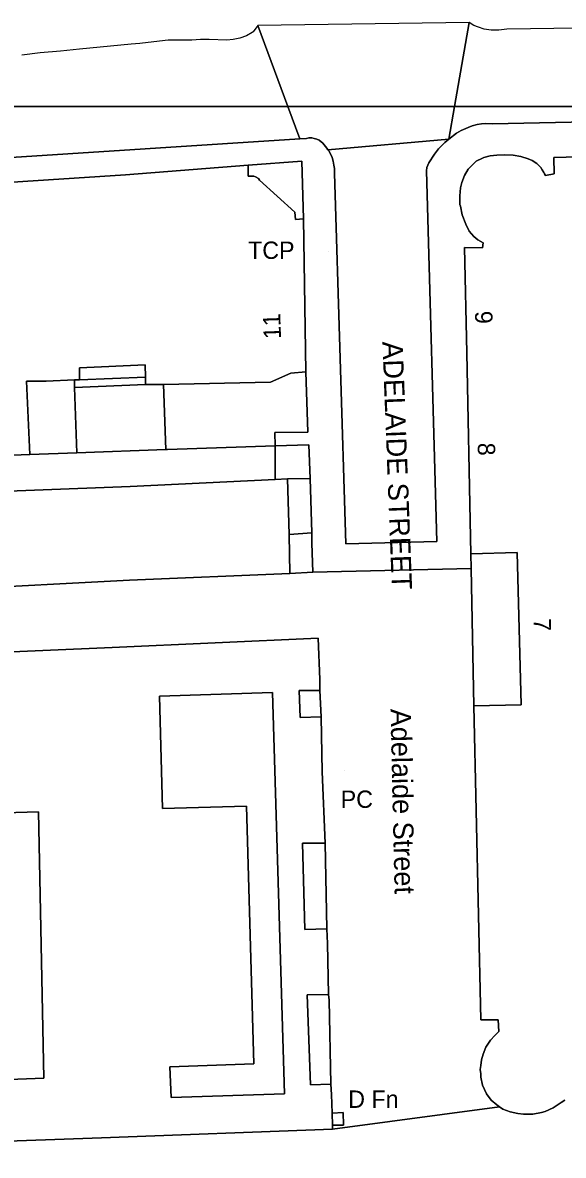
# Model space of a CAD drawing. Extents: x 529240 to 530363, y 179600 to 180767.
# Drawn here: x 530122.5 to 530169.2, y 180523.5 to 180621.2 of the extents above; entities that cross this region are included whole.
import ezdxf

# ---------------------------------------------------------------- set-up
doc = ezdxf.new("R2010")
doc.units = 0
for name, color, linetype in [('Building', 7, 'Continuous'), ('General surface', 7, 'Continuous'), ('Road Or Track', 7, 'Continuous'), ('Roadside', 7, 'Continuous'), ('Structure', 7, 'Continuous'), ('Unclassified', 7, 'Continuous')]:
    doc.layers.add(name, color=color, linetype=linetype)

msp = doc.modelspace()

# ---------------------------------------------------------------- linework, layer by layer
at = {"layer": 'Building'}
for points in [[(530206.3, 180610.65), (530168.35, 180609.6), (530168.4, 180608.2), (530167.65, 180608.05), (530167.55, 180608.2), (530167.5, 180608.3), (530167.35, 180608.55), (530167.25, 180608.75), (530166.9, 180609.1), (530166.5, 180609.35), (530166.15, 180609.5), (530165.5, 180609.7), (530164.85, 180609.8), (530164.1, 180609.85), (530163.45, 180609.8), (530162.85, 180609.75), (530162.3, 180609.6), (530162.2, 180609.55), (530161.65, 180609.3), (530160.95, 180608.6), (530160.65, 180608.05), (530160.4, 180607.45), (530160.3, 180607), (530160.25, 180606.3), (530160.25, 180605.55), (530160.3, 180605.4), (530160.45, 180604.65), (530160.75, 180603.85), (530161.05, 180603.25), (530161.45, 180602.8), (530161.8, 180602.5), (530162.25, 180602.25), (530162.2, 180601.8), (530160.65, 180601.85), (530160.85, 180592.75), (530161.15, 180576.8), (530161.2, 180575.4), (530165.2, 180575.5), (530165.55, 180562.35), (530161.45, 180562.25), (530162.05, 180535.15), (530163.55, 180535.15), (530163.6, 180534.15), (530163.25, 180533.8), (530162.9, 180533.4), (530162.5, 180532.8), (530162.25, 180532.2), (530162.1, 180531.7), (530162.05, 180531.2), (530162, 180530.85), (530162.05, 180530.5), (530162.05, 180530.2), (530162.2, 180529.5), (530162.55, 180528.75), (530162.95, 180528.2), (530163.45, 180527.8), (530163.66, 180527.65), (530163.95, 180527.45), (530164.6, 180527.2), (530165.25, 180527.05), (530165.75, 180527), (530166.55, 180527), (530167.3, 180527.15), (530167.6, 180527.25), (530168.3, 180527.55), (530169, 180528), (530169.3, 180528.2)], [(530161.15, 180576.8), (530160.85, 180592.75), (530160.65, 180601.85), (530162.2, 180601.8), (530162.25, 180602.25), (530161.8, 180602.5), (530161.45, 180602.8), (530161.05, 180603.25), (530160.75, 180603.85), (530160.45, 180604.65), (530160.3, 180605.4), (530160.25, 180605.55), (530160.25, 180606.3), (530160.3, 180607), (530160.4, 180607.45), (530160.65, 180608.05), (530160.95, 180608.6), (530161.65, 180609.3), (530162.2, 180609.55), (530162.3, 180609.6), (530162.85, 180609.75), (530163.45, 180609.8), (530164.1, 180609.85), (530164.85, 180609.8), (530165.5, 180609.7), (530166.15, 180609.5), (530166.5, 180609.35), (530166.9, 180609.1), (530167.25, 180608.75), (530167.35, 180608.55), (530167.5, 180608.3), (530167.55, 180608.2), (530167.65, 180608.05), (530168.4, 180608.2), (530168.35, 180609.6), (530206.3, 180610.65)], [(530091.2, 180605.2), (530113.6, 180606.95), (530131.35, 180608.1), (530141.95, 180608.95)], [(530116.3, 180583.7), (530123.1, 180583.95), (530122.8, 180590.3), (530124.5, 180590.3), (530126.95, 180590.4), (530127.4, 180590.4), (530127.4, 180591.45), (530133.05, 180591.7), (530133.1, 180590.65), (530133.1, 180590), (530134.65, 180590), (530143.9, 180590.2), (530145.65, 180591), (530146.95, 180591.1), (530146.75, 180604.3), (530146.05, 180604.25), (530146, 180604.9), (530142.95, 180607.65), (530142.85, 180607.8), (530142.6, 180607.95), (530142.45, 180608), (530141.95, 180608), (530141.95, 180608.95), (530131.35, 180608.1), (530113.6, 180606.95)], [(530141.95, 180608.95), (530141.95, 180608), (530142.45, 180608), (530142.6, 180607.95), (530142.85, 180607.8), (530142.95, 180607.65), (530146, 180604.9), (530146.05, 180604.25), (530146.75, 180604.3)], [(530146.75, 180604.3), (530146.95, 180591.1)], [(530127.4, 180590.4), (530127.4, 180591.45), (530133.05, 180591.7), (530133.1, 180590.65)], [(530133.1, 180590.65), (530133.1, 180590)], [(530134.65, 180590), (530143.9, 180590.2), (530145.65, 180591), (530146.95, 180591.1)], [(530146.95, 180591.1), (530147.1, 180585.9)], [(530123.1, 180583.95), (530122.8, 180590.3), (530124.5, 180590.3)], [(530124.5, 180590.3), (530126.95, 180590.4)], [(530126.95, 180590.4), (530127.4, 180590.4)], [(530133.1, 180590), (530134.65, 180590)], [(530134.65, 180590), (530134.85, 180584.4)], [(530144.3, 180584.7), (530144.25, 180585.85), (530147.1, 180585.9)], [(530109.95, 180583.45), (530116.3, 180583.7), (530123.1, 180583.95)], [(530123.1, 180583.95), (530127.15, 180584.1)], [(530127.15, 180584.1), (530134.85, 180584.4)], [(530134.85, 180584.4), (530135, 180584.4), (530144.3, 180584.7)], [(530144.3, 180584.7), (530144.3, 180581.8)], [(530144.3, 180581.8), (530145.35, 180581.85)], [(530145.35, 180581.85), (530145.5, 180577.05)], [(530115.95, 180580.1), (530115.95, 180580.6), (530131.75, 180581.2), (530144.3, 180581.8)], [(530145.5, 180577.05), (530145.55, 180573.7)], [(530161.2, 180575.4), (530161.15, 180576.8)], [(530161.45, 180562.25), (530165.55, 180562.35), (530165.2, 180575.5), (530161.2, 180575.4)], [(530161.2, 180575.4), (530161.22, 180574.13)], [(530161.22, 180574.13), (530161.45, 180562.25)], [(530145.55, 180573.7), (530131.7, 180573.1), (530116.4, 180572.3)], [(530135.3, 180528.45), (530135.2, 180531.1), (530142.45, 180531.35), (530141.8, 180553.6), (530134.55, 180553.4), (530134.3, 180563.1), (530144.05, 180563.4), (530145.1, 180528.75), (530135.3, 180528.45)], [(530163.66, 180527.65), (530163.45, 180527.8), (530162.95, 180528.2), (530162.55, 180528.75), (530162.2, 180529.5), (530162.05, 180530.2), (530162.05, 180530.5), (530162, 180530.85), (530162.05, 180531.2), (530162.1, 180531.7), (530162.25, 180532.2), (530162.5, 180532.8), (530162.9, 180533.4), (530163.25, 180533.8), (530163.6, 180534.15), (530163.55, 180535.15), (530162.05, 180535.15), (530161.45, 180562.25)], [(530100.85, 180552.35), (530111.15, 180552.75), (530123.85, 180553.1), (530124.3, 180530.1), (530107.15, 180529.45), (530083.85, 180528.65)], [(530169.3, 180528.2), (530169, 180528), (530168.3, 180527.55), (530167.6, 180527.25), (530167.3, 180527.15), (530166.55, 180527), (530165.75, 180527), (530165.25, 180527.05), (530164.6, 180527.2), (530163.95, 180527.45), (530163.66, 180527.65)]]:
    msp.add_lwpolyline(points, dxfattribs=at)
for points in [[(530146.75, 180604.3), (530146.6, 180609.3), (530141.95, 180608.95), (530141.95, 180608), (530142.45, 180608), (530142.6, 180607.95), (530142.85, 180607.8), (530142.95, 180607.65), (530146, 180604.9), (530146.05, 180604.25)], [(530133.1, 180590.65), (530133.05, 180591.7), (530127.4, 180591.45), (530127.4, 180590.4)], [(530134.65, 180590), (530134.85, 180584.4), (530135, 180584.4), (530144.3, 180584.7), (530144.25, 180585.85), (530147.1, 180585.9), (530146.95, 180591.1), (530145.65, 180591), (530143.9, 180590.2)], [(530115.95, 180580.1), (530115.95, 180580.6), (530131.75, 180581.2), (530144.3, 180581.8), (530144.3, 180584.7), (530135, 180584.4), (530134.85, 180584.4), (530127.15, 180584.1), (530123.1, 180583.95), (530116.3, 180583.7), (530109.95, 180583.45), (530109.9, 180579.85)], [(530145.35, 180581.85), (530144.3, 180581.8), (530131.75, 180581.2), (530115.95, 180580.6), (530115.95, 180580.1), (530116.35, 180572.7), (530116.4, 180572.3), (530131.7, 180573.1), (530145.55, 180573.7), (530145.5, 180577.05)], [(530161.22, 180574.13), (530161.45, 180562.25), (530165.55, 180562.35), (530165.2, 180575.5), (530161.2, 180575.4)], [(530135.3, 180528.45), (530145.1, 180528.75), (530144.05, 180563.4), (530134.3, 180563.1), (530134.55, 180553.4), (530141.8, 180553.6), (530142.45, 180531.35), (530135.2, 180531.1)], [(530083.13, 180550.2), (530083.15, 180549.55), (530083.8, 180530.7), (530083.85, 180528.65), (530107.15, 180529.45), (530124.3, 180530.1), (530123.85, 180553.1), (530111.15, 180552.75), (530100.85, 180552.35), (530096.15, 180552.19), (530093.7, 180552.1), (530092.25, 180552.02), (530083.1, 180551.55), (530083.1, 180551.5), (530083.12, 180550.9)]]:
    msp.add_lwpolyline(points, close=True, dxfattribs=at)
at = {"layer": 'General surface'}
for points in [[(530127.4, 180590.4), (530126.95, 180590.4), (530126.95, 180589.75), (530133.1, 180590), (530133.1, 180590.65)], [(530123.1, 180583.95), (530127.15, 180584.1), (530126.95, 180589.75), (530126.95, 180590.4), (530124.5, 180590.3), (530122.8, 180590.3)], [(530134.85, 180584.4), (530134.65, 180590), (530133.1, 180590), (530126.95, 180589.75), (530127.15, 180584.1)], [(530144.3, 180584.7), (530144.3, 180581.8), (530145.35, 180581.85), (530147.3, 180581.9), (530147.2, 180584.8)], [(530147.45, 180577.2), (530147.3, 180581.9), (530145.35, 180581.85), (530145.5, 180577.05)], [(530147.55, 180573.8), (530147.45, 180576.3), (530147.45, 180577.2), (530145.5, 180577.05), (530145.55, 180573.7)], [(530135.3, 180528.45), (530145.1, 180528.75), (530144.05, 180563.4), (530134.3, 180563.1), (530134.55, 180553.4), (530141.8, 180553.6), (530142.45, 180531.35), (530135.2, 180531.1)], [(530148.25, 180561.3), (530148.15, 180563.6), (530146.35, 180563.6), (530146.45, 180561.25)], [(530148.75, 180543), (530148.6, 180550.4), (530146.65, 180550.4), (530146.85, 180542.95)], [(530148.9, 180537.35), (530147.05, 180537.3), (530147.35, 180529.55), (530149.1, 180529.6), (530148.95, 180536.85)], [(530149.2, 180527.1), (530149.25, 180526.05), (530150.2, 180526.05), (530150.15, 180527.15)]]:
    msp.add_lwpolyline(points, close=True, dxfattribs=at)
for points in [[(530108.2, 180566.35), (530130.2, 180567.3), (530148, 180568.1), (530148.15, 180564.55), (530148.15, 180563.6), (530148.25, 180561.3), (530148.35, 180556.55), (530148.6, 180550.4), (530148.75, 180543), (530148.8, 180541.75), (530148.9, 180537.35), (530148.95, 180536.85), (530149.1, 180529.6), (530149.15, 180528.7), (530149.2, 180527.1), (530150.15, 180527.15), (530150.2, 180526.05), (530149.25, 180526.05), (530149.25, 180525.7), (530163.66, 180527.65), (530163.45, 180527.8), (530162.95, 180528.2), (530162.55, 180528.75), (530162.2, 180529.5), (530162.05, 180530.2), (530162.05, 180530.5), (530162, 180530.85), (530162.05, 180531.2), (530162.1, 180531.7), (530162.25, 180532.2), (530162.5, 180532.8), (530162.9, 180533.4), (530163.25, 180533.8), (530163.6, 180534.15), (530163.55, 180535.15), (530162.05, 180535.15), (530161.45, 180562.25), (530161.22, 180574.13), (530147.55, 180573.8), (530145.55, 180573.7), (530131.7, 180573.1), (530116.4, 180572.3)], [(530118.75, 180524.6), (530129.3, 180524.95), (530149.25, 180525.7), (530149.25, 180526.05), (530149.2, 180527.1), (530149.15, 180528.7), (530149.1, 180529.6), (530147.35, 180529.55), (530147.05, 180537.3), (530148.9, 180537.35), (530148.8, 180541.75), (530148.75, 180543), (530146.85, 180542.95), (530146.65, 180550.4), (530148.6, 180550.4), (530148.35, 180556.55), (530148.25, 180561.3), (530146.45, 180561.25), (530146.35, 180563.6), (530148.15, 180563.6), (530148.15, 180564.55), (530148, 180568.1), (530130.2, 180567.3), (530108.2, 180566.35)], [(530111.15, 180552.75), (530123.85, 180553.1), (530124.3, 180530.1), (530107.15, 180529.45)]]:
    msp.add_lwpolyline(points, dxfattribs=at)
at = {"layer": 'Road Or Track'}
for points in [[(530077.844, 180614), (530145.396, 180614), (530142.8, 180621), (530142.4, 180620.45), (530142.3, 180620.4), (530141.8, 180620.1), (530141.25, 180619.9), (530140.65, 180619.8), (530140.1, 180619.75), (530138.6, 180619.8), (530137.85, 180619.8), (530137.1, 180619.75), (530135.05, 180619.75), (530134.3, 180619.65), (530132.6, 180619.45), (530131.85, 180619.4), (530127.4, 180618.95), (530125.75, 180618.8), (530124, 180618.65), (530122.4, 180618.45)], [(530176.5, 180620.85), (530164.3, 180620.7), (530163.6, 180620.6), (530162.95, 180620.6), (530162.35, 180620.7), (530161.85, 180620.85), (530161.45, 180621), (530161.05, 180621.25), (530159.788, 180614), (530216, 180614)], [(530159.3, 180611.2), (530159.95, 180611.7), (530160.35, 180611.95), (530160.95, 180612.2), (530161.3, 180612.35), (530161.75, 180612.45), (530162.1, 180612.5), (530162.5, 180612.55), (530163.05, 180612.5), (530216, 180613.649)], [(530077.08, 180607.88), (530081.76, 180607.68), (530089.91, 180608), (530100.51, 180608.25), (530146.43, 180611.21)], [(530146.43, 180611.21), (530147, 180611.25), (530147.2, 180611.3), (530147.45, 180611.3), (530147.65, 180611.25), (530147.9, 180611.2), (530148.1, 180611.1), (530148.4, 180610.85), (530148.75, 180610.4), (530148.85, 180610.27)], [(530148.85, 180610.27), (530148.95, 180610.15), (530149.2, 180609.6), (530149.3, 180609.3), (530149.35, 180608.95), (530149.4, 180608.65), (530149.4, 180608.25), (530150.4, 180576.25), (530158.25, 180576.45), (530157.35, 180608.45), (530157.4, 180608.75), (530157.55, 180609.15), (530158.05, 180609.9), (530158.4, 180610.35), (530158.95, 180610.9), (530159.3, 180611.2)]]:
    msp.add_lwpolyline(points, dxfattribs=at)
for points in [[(530145.396, 180614), (530159.788, 180614), (530161.05, 180621.25), (530142.8, 180621)], [(530077.844, 180614), (530078.05, 180613.96), (530079.22, 180613.72), (530080.2, 180613.52), (530080.81, 180613.12), (530081, 180612.56), (530080.84, 180612), (530080.39, 180611.61), (530079.8, 180611.56), (530078.82, 180611.76), (530077.65, 180612), (530077.08, 180612.11), (530077.08, 180607.88), (530081.76, 180607.68), (530089.91, 180608), (530100.51, 180608.25), (530146.43, 180611.21), (530145.396, 180614)], [(530145.396, 180614), (530146.43, 180611.21), (530147, 180611.25), (530147.2, 180611.3), (530147.45, 180611.3), (530147.65, 180611.25), (530147.9, 180611.2), (530148.1, 180611.1), (530148.4, 180610.85), (530148.75, 180610.4), (530148.85, 180610.27), (530159.3, 180611.2), (530159.788, 180614)], [(530159.788, 180614), (530159.3, 180611.2), (530159.95, 180611.7), (530160.35, 180611.95), (530160.95, 180612.2), (530161.3, 180612.35), (530161.75, 180612.45), (530162.1, 180612.5), (530162.5, 180612.55), (530163.05, 180612.5), (530216, 180613.649), (530216, 180614)], [(530148.85, 180610.27), (530148.95, 180610.15), (530149.2, 180609.6), (530149.3, 180609.3), (530149.35, 180608.95), (530149.4, 180608.65), (530149.4, 180608.25), (530150.4, 180576.25), (530158.25, 180576.45), (530157.35, 180608.45), (530157.4, 180608.75), (530157.55, 180609.15), (530158.05, 180609.9), (530158.4, 180610.35), (530158.95, 180610.9), (530159.3, 180611.2)]]:
    msp.add_lwpolyline(points, close=True, dxfattribs=at)
at = {"layer": 'Roadside'}
for points in [[(530216, 180613.649), (530163.05, 180612.5), (530162.5, 180612.55), (530162.1, 180612.5), (530161.75, 180612.45), (530161.3, 180612.35), (530160.95, 180612.2), (530160.35, 180611.95), (530159.95, 180611.7), (530159.3, 180611.2), (530158.95, 180610.9), (530158.4, 180610.35), (530158.05, 180609.9), (530157.55, 180609.15), (530157.4, 180608.75), (530157.35, 180608.45), (530158.25, 180576.45), (530150.4, 180576.25), (530149.4, 180608.25), (530149.4, 180608.65), (530149.35, 180608.95), (530149.3, 180609.3), (530149.2, 180609.6), (530148.95, 180610.15), (530148.85, 180610.27), (530148.75, 180610.4), (530148.4, 180610.85), (530148.1, 180611.1), (530147.9, 180611.2), (530147.65, 180611.25), (530147.45, 180611.3), (530147.2, 180611.3), (530147, 180611.25), (530146.43, 180611.21), (530100.51, 180608.25)], [(530113.6, 180606.95), (530131.35, 180608.1), (530141.95, 180608.95), (530146.6, 180609.3), (530146.75, 180604.3), (530146.95, 180591.1), (530147.1, 180585.9), (530144.25, 180585.85), (530144.3, 180584.7), (530147.2, 180584.8), (530147.3, 180581.9), (530147.45, 180577.2), (530147.45, 180576.3), (530147.55, 180573.8), (530161.22, 180574.13), (530161.2, 180575.4), (530161.15, 180576.8), (530160.85, 180592.75), (530160.65, 180601.85), (530162.2, 180601.8), (530162.25, 180602.25), (530161.8, 180602.5), (530161.45, 180602.8), (530161.05, 180603.25), (530160.75, 180603.85), (530160.45, 180604.65), (530160.3, 180605.4), (530160.25, 180605.55), (530160.25, 180606.3), (530160.3, 180607), (530160.4, 180607.45), (530160.65, 180608.05), (530160.95, 180608.6), (530161.65, 180609.3), (530162.2, 180609.55), (530162.3, 180609.6), (530162.85, 180609.75), (530163.45, 180609.8), (530164.1, 180609.85), (530164.85, 180609.8), (530165.5, 180609.7), (530166.15, 180609.5), (530166.5, 180609.35), (530166.9, 180609.1), (530167.25, 180608.75), (530167.35, 180608.55), (530167.5, 180608.3), (530167.55, 180608.2), (530167.65, 180608.05), (530168.4, 180608.2), (530168.35, 180609.6), (530206.3, 180610.65)], [(530169.3, 180528.2), (530169, 180528), (530168.3, 180527.55), (530167.6, 180527.25), (530167.3, 180527.15), (530166.55, 180527), (530165.75, 180527), (530165.25, 180527.05), (530164.6, 180527.2), (530163.95, 180527.45), (530163.66, 180527.65), (530149.25, 180525.7), (530129.3, 180524.95), (530118.75, 180524.6)]]:
    msp.add_lwpolyline(points, dxfattribs=at)
at = {"layer": 'Structure'}
for p, q in [((530148.9, 180601.45), (530148.9, 180601.45)), ((530150.3, 180556.7), (530150.3, 180556.7))]:
    msp.add_line(p, q, dxfattribs=at)
at = {"layer": 'Unclassified'}
for points in [[(530145.396, 180614), (530142.8, 180621)], [(530161.05, 180621.25), (530159.788, 180614)], [(530146.43, 180611.21), (530145.396, 180614)], [(530159.788, 180614), (530159.3, 180611.2)], [(530159.3, 180611.2), (530148.85, 180610.27)], [(530141.95, 180608.95), (530146.6, 180609.3), (530146.75, 180604.3)], [(530127.4, 180590.4), (530133.1, 180590.65)], [(530126.95, 180590.4), (530126.95, 180589.75)], [(530126.95, 180589.75), (530133.1, 180590)], [(530126.95, 180589.75), (530127.15, 180584.1)], [(530144.3, 180584.7), (530147.2, 180584.8)], [(530147.2, 180584.8), (530147.3, 180581.9)], [(530145.35, 180581.85), (530147.3, 180581.9)], [(530147.3, 180581.9), (530147.45, 180577.2)], [(530145.5, 180577.05), (530147.45, 180577.2)], [(530147.45, 180577.2), (530147.45, 180576.3)], [(530147.45, 180576.3), (530147.55, 180573.8)], [(530147.55, 180573.8), (530161.22, 180574.13)], [(530147.55, 180573.8), (530145.55, 180573.7)], [(530084.45, 180565.4), (530108.2, 180566.35), (530130.2, 180567.3), (530148, 180568.1), (530148.15, 180564.55)], [(530148.15, 180564.55), (530148.15, 180563.6)], [(530148.15, 180563.6), (530146.35, 180563.6), (530146.45, 180561.25), (530148.25, 180561.3)], [(530148.15, 180563.6), (530148.25, 180561.3)], [(530148.25, 180561.3), (530148.35, 180556.55)], [(530148.35, 180556.55), (530148.6, 180550.4)], [(530148.6, 180550.4), (530146.65, 180550.4), (530146.85, 180542.95), (530148.75, 180543)], [(530148.6, 180550.4), (530148.75, 180543)], [(530148.75, 180543), (530148.8, 180541.75)], [(530148.8, 180541.75), (530148.9, 180537.35)], [(530148.9, 180537.35), (530147.05, 180537.3), (530147.35, 180529.55), (530149.1, 180529.6)], [(530148.9, 180537.35), (530148.95, 180536.85)], [(530148.95, 180536.85), (530149.1, 180529.6)], [(530149.1, 180529.6), (530149.15, 180528.7)], [(530149.15, 180528.7), (530149.2, 180527.1)], [(530149.2, 180527.1), (530150.15, 180527.15), (530150.2, 180526.05), (530149.25, 180526.05)], [(530149.2, 180527.1), (530149.25, 180526.05)], [(530149.25, 180525.7), (530163.66, 180527.65)], [(530149.25, 180525.7), (530129.3, 180524.95), (530118.75, 180524.6), (530109.35, 180524.25), (530099.6, 180523.95), (530084.05, 180523.45), (530083.95, 180523.8)], [(530149.25, 180526.05), (530149.25, 180525.7)]]:
    msp.add_lwpolyline(points, dxfattribs=at)

# ---------------------------------------------------------------- texts
at = {"layer": 'Road Or Track'}
msp.add_text('ADELAIDE STREET', height=1.75, rotation=272.2, dxfattribs=at).set_placement((530153.55, 180593.7))
at = {"layer": 'Structure'}
for s, p in [('TCP', (530141.95, 180600.85)), ('D Fn', (530150.6, 180527.55))]:
    msp.add_text(s, height=1.5, dxfattribs=at).set_placement(p)
at = {"layer": 'Unclassified'}
for s, height, rotation, p in [('11', 1.5, 92, (530144.8, 180593.95)), ('9', 1.5, 272.4, (530161.54, 180596.33)), ('8', 1.5, 271.5, (530161.78, 180584.96)), ('7', 1.5, 271.6, (530166.6, 180569.8)), ('Adelaide Street', 1.75, 271.3, (530154.25, 180562))]:
    msp.add_text(s, height=height, rotation=rotation, dxfattribs=at).set_placement(p)
msp.add_text('PC', height=1.5, dxfattribs=at).set_placement((530149.95, 180553.45))

doc.saveas('drawing.dxf')
